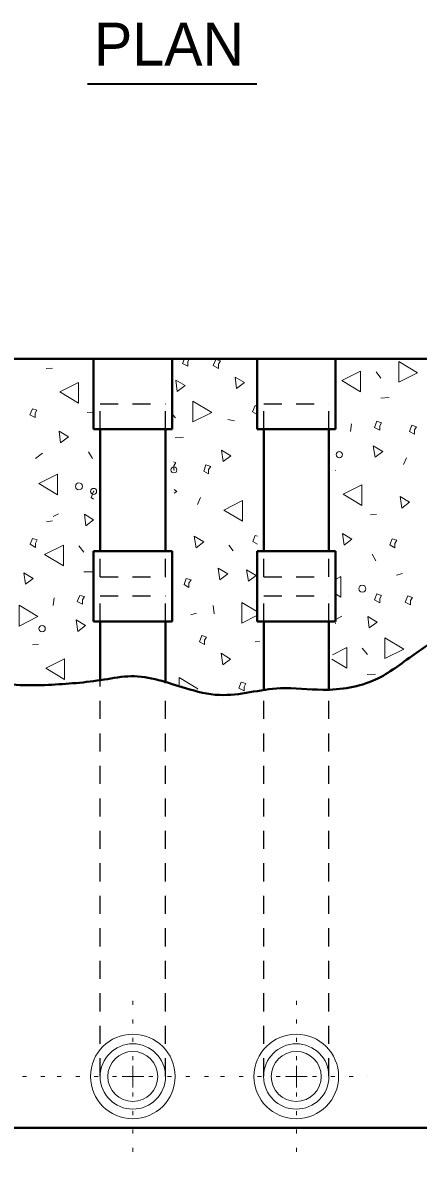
# Model space of a CAD drawing. Extents: x 312583 to 312854, y 144419 to 144597.
# Drawn here: x 312753.44 to 312763.3, y 144519.54 to 144547.78 of the extents above; entities that cross this region are included whole.
import ezdxf
from ezdxf.enums import TextEntityAlignment as Align

# ---------------------------------------------------------------- set-up
doc = ezdxf.new("R2010")
doc.units = 0
doc.header["$LTSCALE"] = 0.3
doc.header["$PDMODE"] = 32
doc.header["$PDSIZE"] = 0.15
doc.linetypes.add('DOTTED', pattern=[1.5, 0.3, -1.2])
doc.linetypes.add('SHORT_DASHED', pattern=[2.7, 1.5, -1.2])
doc.layers.add('1', color=7, linetype='Continuous', lineweight=25)
doc.layers.add('2', color=7, linetype='Continuous', lineweight=13)

msp = doc.modelspace()

# ---------------------------------------------------------------- linework, layer by layer
at = {"layer": '1', "lineweight": 40}
for p, q in [((312740.86, 144539.3938), (312771.5267, 144539.3938)), ((312755.212, 144537.6381), (312755.212, 144539.3938)), ((312757.167, 144537.6381), (312757.167, 144539.3938)), ((312759.2907, 144537.6381), (312759.2907, 144539.3938)), ((312761.238, 144537.6381), (312761.238, 144539.3938)), ((312755.212, 144537.6381), (312757.167, 144537.6381)), ((312755.373, 144534.6021), (312755.373, 144537.6381)), ((312757.006, 144534.6021), (312757.006, 144537.6381)), ((312759.2907, 144537.6381), (312761.238, 144537.6381)), ((312759.4517, 144534.6021), (312759.4517, 144537.6381)), ((312761.077, 144534.6021), (312761.077, 144537.6381)), ((312755.212, 144532.8464), (312755.212, 144534.6021)), ((312755.212, 144534.6021), (312757.167, 144534.6021)), ((312757.167, 144532.8464), (312757.167, 144534.6021)), ((312759.2907, 144532.8464), (312759.2907, 144534.6021)), ((312759.2907, 144534.6021), (312761.238, 144534.6021)), ((312761.238, 144532.8464), (312761.238, 144534.6021)), ((312755.212, 144532.8464), (312757.167, 144532.8464)), ((312755.373, 144531.3898), (312755.373, 144532.8464)), ((312757.006, 144531.3054), (312757.006, 144532.8464)), ((312759.2907, 144532.8464), (312761.238, 144532.8464)), ((312759.4517, 144531.1368), (312759.4517, 144532.8464)), ((312761.077, 144531.1751), (312761.077, 144532.8464)), ((312740.216, 144520.2271), (312772.163, 144520.2271))]:
    msp.add_line(p, q, dxfattribs=at)
at = {"layer": '1', "linetype": 'SHORT_DASHED'}
for p, q in [((312755.373, 144537.6381), (312755.373, 144538.2744)), ((312755.373, 144538.2744), (312757.006, 144538.2744)), ((312757.006, 144537.6381), (312757.006, 144538.2744)), ((312759.4517, 144538.2744), (312761.077, 144538.2744)), ((312759.4517, 144537.6381), (312759.4517, 144538.2744)), ((312761.077, 144537.6381), (312761.077, 144538.2744)), ((312755.373, 144533.9581), (312755.373, 144534.6021)), ((312757.006, 144533.9581), (312757.006, 144534.6021)), ((312759.4517, 144533.9581), (312759.4517, 144534.6021)), ((312761.077, 144533.9581), (312761.077, 144534.6021)), ((312755.373, 144533.9581), (312757.006, 144533.9581)), ((312759.4517, 144533.9581), (312761.077, 144533.9581)), ((312755.373, 144532.8464), (312755.373, 144533.4828)), ((312755.373, 144533.4828), (312757.006, 144533.4828)), ((312757.006, 144532.8464), (312757.006, 144533.4828)), ((312759.4517, 144533.4828), (312761.077, 144533.4828)), ((312759.4517, 144532.8464), (312759.4517, 144533.4828)), ((312761.077, 144532.8464), (312761.077, 144533.4828)), ((312755.373, 144521.5074), (312755.373, 144531.3898)), ((312759.4517, 144521.5074), (312759.4517, 144531.1368)), ((312761.077, 144521.5074), (312761.077, 144531.1751)), ((312757.006, 144521.5074), (312757.006, 144531.0831))]:
    msp.add_line(p, q, dxfattribs=at)
at = {"layer": '1', "lineweight": 13}
for centre, radius in [((312756.1895, 144521.5036), 1.0542), ((312760.2625, 144521.5036), 1.0542), ((312756.1895, 144521.5036), 0.8146), ((312756.1895, 144521.5036), 0.6232), ((312760.2625, 144521.5036), 0.8146), ((312760.2625, 144521.5036), 0.6232)]:
    msp.add_circle(centre, radius, dxfattribs=at)
at = {"layer": '1', "lineweight": 40}
msp.add_spline([(312747.07, 144539.3938), (312747.4074, 144536.8408), (312748.0437, 144535.6218), (312748.887, 144535.3688), (312749.393, 144535.1541), (312750.8727, 144534.0578), (312751.0874, 144533.5518), (312751.1717, 144533.3371), (312751.509, 144532.4938), (312752.0534, 144531.9418), (312752.4367, 144531.5201), (312753.28, 144531.2671), (312754.085, 144531.2671), (312755.4727, 144531.3974), (312756.1474, 144531.4818), (312757.5044, 144531.1828), (312758.3477, 144531.0141), (312759.8657, 144531.1828), (312760.9237, 144531.1444), (312762.2347, 144531.3974), (312763.2007, 144532.0261), (312764.0057, 144532.7084), (312764.5117, 144534.1421), (312764.7264, 144534.5638), (312764.8107, 144535.1158), (312764.7264, 144535.8288), (312764.7264, 144536.5878), (312764.8107, 144537.3084), (312765.2324, 144538.2821), (312764.7647, 144538.9568), (312764.9334, 144539.3938)], degree=3, dxfattribs=at)
at = {"layer": '2', "lineweight": 35}
msp.add_line((312755.0631, 144546.2521), (312759.2836, 144546.2521), dxfattribs=at)
at = {"layer": '2'}
for p, q in [((312757.558, 144539.3171), (312757.5964, 144539.3938)), ((312754.0314, 144539.1561), (312754.1847, 144539.1638)), ((312762.25, 144539.0718), (312762.3727, 144538.9108)), ((312762.3727, 144538.4124), (312762.5797, 144538.4278)), ((312755.051, 144538.0598), (312755.2044, 144538.0674)), ((312757.19, 144537.9984), (312757.2514, 144537.9218)), ((312758.5547, 144537.8834), (312758.7234, 144537.8451)), ((312761.6137, 144537.5844), (312761.6367, 144537.7761)), ((312757.2437, 144537.4234), (312757.4507, 144537.4388)), ((312753.9394, 144537.0401), (312753.763, 144536.9098)), ((312755.0894, 144537.0784), (312755.1814, 144536.9098)), ((312763.009, 144536.9251), (312762.9324, 144536.7564)), ((312757.213, 144536.6261), (312757.213, 144536.7258)), ((312761.238, 144536.6108), (312761.2457, 144536.6108)), ((312757.88, 144535.9361), (312757.8034, 144535.7674)), ((312754.039, 144535.3304), (312754.1847, 144535.3534)), ((312754.2077, 144535.4608), (312754.338, 144535.5298)), ((312762.112, 144535.5068), (312762.2654, 144535.5144)), ((312754.844, 144534.7324), (312754.9667, 144534.5714)), ((312758.5854, 144534.7478), (312758.6927, 144534.6098)), ((312762.1504, 144534.5254), (312762.2424, 144534.3568)), ((312754.9667, 144534.0808), (312755.1737, 144534.0884)), ((312762.7637, 144534.0041), (312762.9094, 144534.0424)), ((312754.2077, 144533.2451), (312754.2307, 144533.4368)), ((312761.238, 144533.5364), (312761.376, 144533.4521)), ((312758.1944, 144533.2451), (312758.2174, 144533.0381)), ((312759.2984, 144533.0841), (312758.9074, 144533.3218)), ((312757.6347, 144533.0151), (312757.7804, 144533.0534)), ((312761.2304, 144532.8004), (312761.2457, 144532.8081)), ((312761.2687, 144532.9078), (312761.399, 144532.9768)), ((312753.694, 144532.2638), (312753.8397, 144532.2714)), ((312759.237, 144532.3404), (312759.3444, 144532.3481)), ((312761.905, 144532.1794), (312762.0354, 144532.0261)), ((312761.146, 144531.9111), (312761.5217, 144531.6811)), ((312757.3434, 144531.4511), (312757.3434, 144531.2671)), ((312762.0277, 144531.5278), (312762.2347, 144531.5354)), ((312756.1934, 144521.4998), (312756.1934, 144521.7681)), ((312760.2644, 144521.4998), (312760.2644, 144521.7681)), ((312756.1934, 144521.4998), (312755.925, 144521.4998)), ((312756.1934, 144521.4998), (312756.4617, 144521.4998)), ((312756.1934, 144521.4998), (312756.1934, 144521.2314)), ((312760.2644, 144521.4998), (312759.996, 144521.4998)), ((312760.2644, 144521.4998), (312760.5327, 144521.4998)), ((312760.2644, 144521.4998), (312760.2644, 144521.2314))]:
    msp.add_line(p, q, dxfattribs=at)
at = {"layer": '2', "linetype": 'DOTTED'}
for p, q in [((312756.1934, 144521.9061), (312756.1934, 144523.6081)), ((312760.2644, 144521.9061), (312760.2644, 144523.6081)), ((312752.521, 144521.4998), (312754.1617, 144521.4998)), ((312755.787, 144521.4998), (312754.1617, 144521.4998)), ((312756.592, 144521.4998), (312758.317, 144521.4998)), ((312759.858, 144521.4998), (312758.317, 144521.4998)), ((312760.663, 144521.4998), (312762.043, 144521.4998)), ((312756.1934, 144521.1011), (312756.1934, 144519.5371)), ((312760.2644, 144521.1011), (312760.2644, 144519.5371))]:
    msp.add_line(p, q, dxfattribs=at)
at = {"layer": '2'}
for points in [[(312757.4737, 144539.3938), (312757.4277, 144539.2788), (312757.558, 144539.2098), (312757.558, 144539.3171)], [(312759.2907, 144538.2054), (312759.237, 144538.2284), (312759.1757, 144538.0751), (312759.2907, 144538.0061)], [(312757.213, 144536.7258), (312757.259, 144536.8101), (312757.2054, 144536.8254)], [(312755.212, 144536.0894), (312755.1507, 144535.9361), (312755.212, 144535.8978)], [(312757.2207, 144536.0434), (312757.2897, 144536.0894), (312757.2207, 144536.1354)], [(312759.2984, 144534.9778), (312759.237, 144534.9931), (312759.1834, 144534.8398), (312759.2984, 144534.7784)], [(312761.376, 144533.4521), (312761.376, 144533.9658), (312761.238, 144533.8968)], [(312758.9074, 144533.3218), (312758.9074, 144532.8081), (312759.2984, 144533.0074)], [(312761.5217, 144531.6811), (312761.5217, 144532.1948), (312761.1614, 144532.0184)], [(312757.7957, 144531.1598), (312757.811, 144531.1674), (312757.3434, 144531.4511)]]:
    msp.add_lwpolyline(points, dxfattribs=at)
for points in [[(312758.3247, 144539.2634), (312758.3707, 144539.3478), (312758.2557, 144539.3784), (312758.1944, 144539.2328), (312758.3247, 144539.1561)], [(312762.8174, 144539.3324), (312762.8174, 144538.8111), (312763.285, 144539.0488)], [(312761.8667, 144538.5734), (312761.8667, 144539.0871), (312761.399, 144538.8571)], [(312754.8364, 144538.2898), (312754.8364, 144538.8034), (312754.3687, 144538.5734)], [(312757.2974, 144538.5811), (312757.4967, 144538.7268), (312757.259, 144538.8648)], [(312758.777, 144538.6578), (312758.9687, 144538.8034), (312758.7387, 144538.9414)], [(312757.6884, 144538.3358), (312757.6884, 144537.8221), (312758.156, 144538.0598)], [(312753.7554, 144538.0368), (312753.8014, 144538.1134), (312753.6864, 144538.1518), (312753.625, 144537.9984), (312753.7554, 144537.9294)], [(312762.342, 144537.7224), (312762.388, 144537.7991), (312762.273, 144537.8374), (312762.2117, 144537.6841), (312762.342, 144537.6151)], [(312763.2084, 144537.6228), (312763.262, 144537.6994), (312763.1394, 144537.7378), (312763.0857, 144537.5844), (312763.2084, 144537.5154)], [(312754.3917, 144537.3008), (312754.5834, 144537.4464), (312754.3534, 144537.5921)], [(312758.4397, 144536.8331), (312758.6314, 144536.9788), (312758.4014, 144537.1168)], [(312762.227, 144536.9404), (312762.4187, 144537.0861), (312762.181, 144537.2241)], [(312754.315, 144536.0051), (312754.315, 144536.5188), (312753.8474, 144536.2888)], [(312758.0794, 144536.6338), (312758.133, 144536.7104), (312758.0104, 144536.7488), (312757.9567, 144536.5954), (312758.0794, 144536.5264)], [(312761.8974, 144535.7368), (312761.8974, 144536.2504), (312761.4297, 144536.0204)], [(312762.894, 144535.6754), (312763.0857, 144535.8211), (312762.848, 144535.9591)], [(312758.9227, 144535.3458), (312758.9227, 144535.8594), (312758.455, 144535.6218)], [(312755.0204, 144535.2308), (312755.212, 144535.3841), (312754.982, 144535.5221)], [(312753.763, 144534.8014), (312753.809, 144534.8858), (312753.694, 144534.9164), (312753.6327, 144534.7708), (312753.763, 144534.6941)], [(312757.765, 144534.6864), (312757.9567, 144534.8321), (312757.719, 144534.9701)], [(312761.4527, 144534.7478), (312761.6444, 144534.9011), (312761.4144, 144535.0391)], [(312762.7177, 144534.7938), (312762.7714, 144534.8704), (312762.6487, 144534.9088), (312762.595, 144534.7554), (312762.7177, 144534.6864)], [(312754.4607, 144534.2341), (312754.4607, 144534.7478), (312753.993, 144534.5178)], [(312753.5177, 144533.7741), (312753.7094, 144533.9198), (312753.4717, 144534.0578)], [(312758.3554, 144533.8891), (312758.5547, 144534.0348), (312758.317, 144534.1728)], [(312759.0684, 144533.8508), (312759.26, 144533.9964), (312759.0224, 144534.1344)], [(312757.5887, 144533.8048), (312757.6424, 144533.8814), (312757.5197, 144533.9198), (312757.466, 144533.7664), (312757.5887, 144533.6974)], [(312754.936, 144533.3831), (312754.982, 144533.4674), (312754.867, 144533.4981), (312754.8057, 144533.3448), (312754.936, 144533.2758)], [(312762.342, 144533.4214), (312762.388, 144533.4981), (312762.273, 144533.5364), (312762.2117, 144533.3831), (312762.342, 144533.3141)], [(312763.1087, 144533.3678), (312763.1547, 144533.4444), (312763.0397, 144533.4828), (312762.9784, 144533.3294), (312763.1087, 144533.2604)], [(312753.3567, 144533.2528), (312753.3567, 144532.7314), (312753.8244, 144532.9691)], [(312754.821, 144532.6011), (312755.0127, 144532.7468), (312754.775, 144532.8848)], [(312762.0814, 144532.6854), (312762.2807, 144532.8311), (312762.043, 144532.9691)], [(312757.9797, 144532.3788), (312758.0257, 144532.4554), (312757.9107, 144532.4938), (312757.8494, 144532.3404), (312757.9797, 144532.2714)], [(312762.4724, 144532.4401), (312762.4724, 144531.9264), (312762.94, 144532.1564)], [(312758.432, 144531.7654), (312758.6237, 144531.9111), (312758.3937, 144532.0568)], [(312754.4914, 144531.3974), (312754.4914, 144531.9188), (312754.0237, 144531.6811)], [(312758.961, 144531.2211), (312759.007, 144531.2978), (312758.892, 144531.3361), (312758.8307, 144531.1828), (312758.961, 144531.1138)]]:
    msp.add_lwpolyline(points, close=True, dxfattribs=at)
for centre, radius in [((312761.3357, 144537.0073), 0.0784), ((312754.8471, 144536.2162), 0.0865), ((312761.9086, 144533.6643), 0.0865), ((312753.9296, 144532.6694), 0.0784)]:
    msp.add_circle(centre, radius, dxfattribs=at)
for p in [(312757.213, 144536.6261), (312755.212, 144536.0894)]:
    msp.add_point(p, dxfattribs=at)

# ---------------------------------------------------------------- texts
msp.add_text('PLAN', height=1.07, dxfattribs=at).set_placement((312757.0911, 144546.7062), align=Align.CENTER)

doc.saveas('drawing.dxf')
